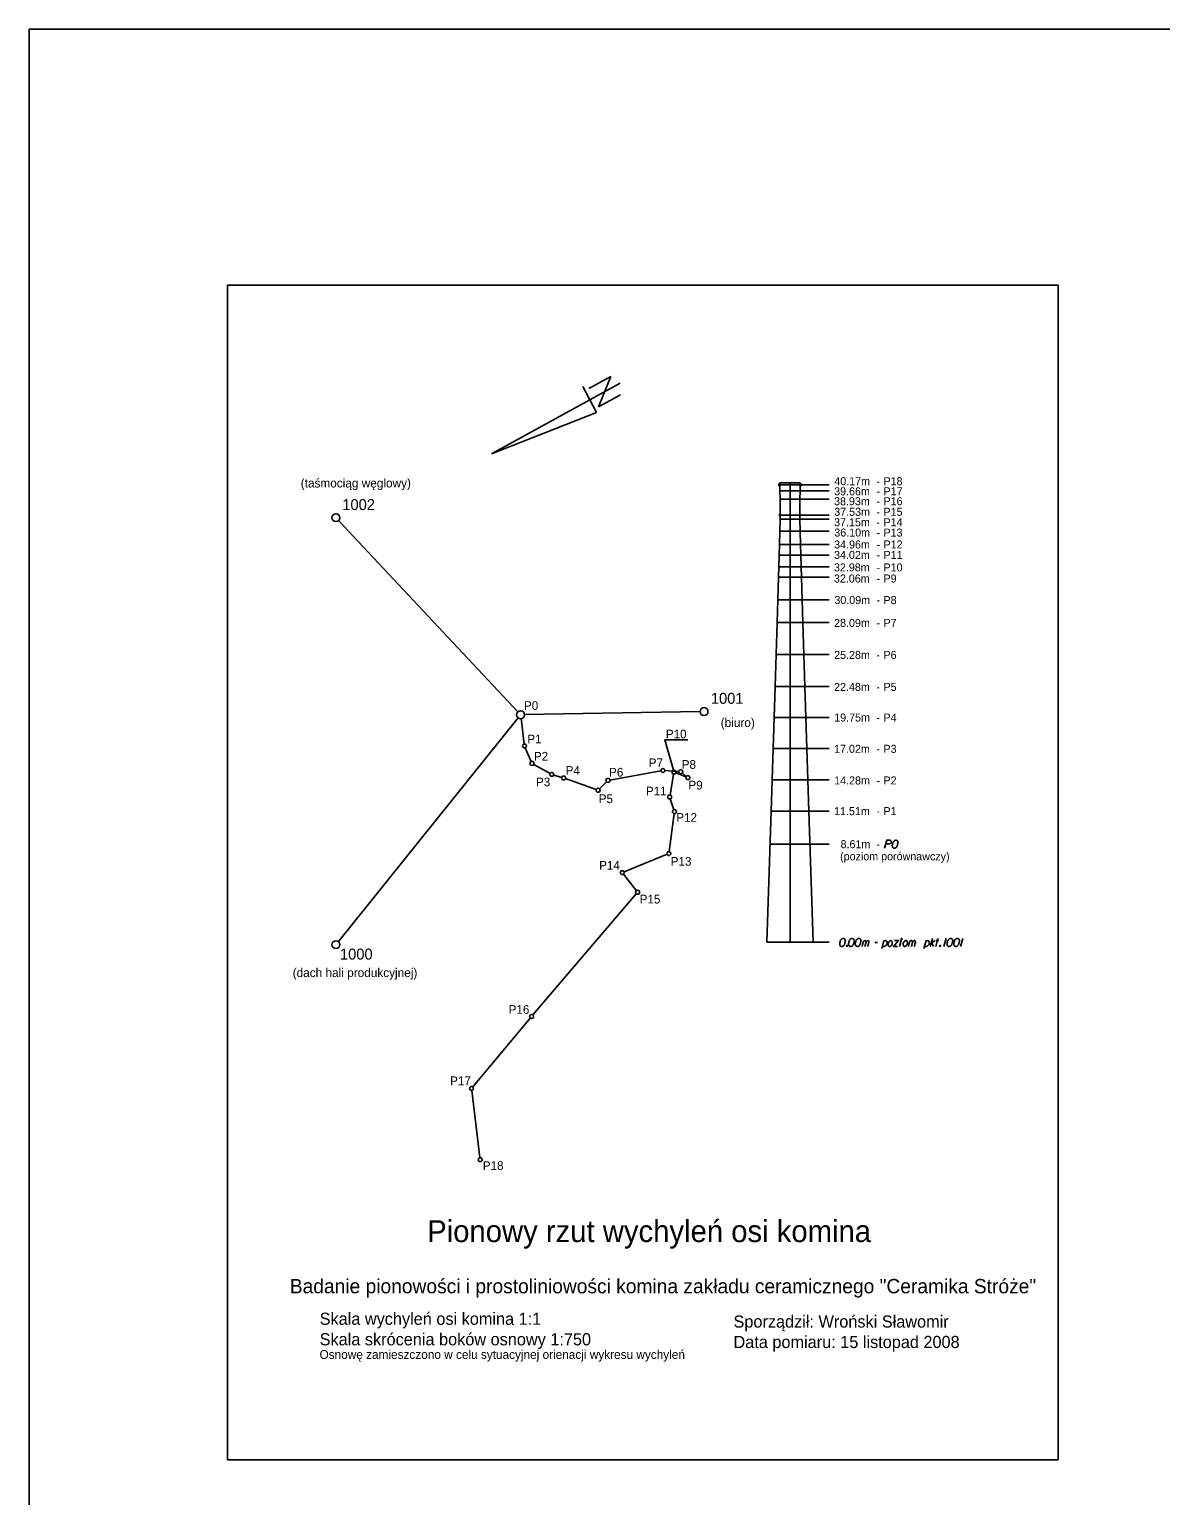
# Model space of a CAD drawing. Extents: x 138 to 264, y -75 to 121.
# Drawn here: x 137.94 to 166.54, y 1.58 to 38.66 of the extents above; entities that cross this region are included whole.
import ezdxf

# ---------------------------------------------------------------- set-up
doc = ezdxf.new("R2010")
doc.units = 0
for name, color, linetype in [('15 listopad 2008', 7, 'Continuous'), ('Opisy', 7, 'Continuous'), ('Ramka do drukowania', 7, 'Continuous'), ('Standart wykresów', 7, 'Continuous'), ('Wykresy 15 listopad 2008', 7, 'Continuous'), ('Wykresy 4 maj 2008', 7, 'Continuous')]:
    doc.layers.add(name, color=color, linetype=linetype)

msp = doc.modelspace()

# ---------------------------------------------------------------- linework, layer by layer
at = {"layer": '15 listopad 2008'}
msp.add_lwpolyline([(137.936, 38.661), (264.389, 38.661), (264.389, -75.347), (137.936, -75.347)], close=True, dxfattribs=at)
msp.add_lwpolyline([(154.222, 19.928), (154.003, 20.696), (154.583, 20.696)], dxfattribs=at)
at = {"layer": 'Opisy'}
for p, q in [((156.89, 27.165), (156.89, 27.141)), ((156.912, 27.165), (156.89, 27.165)), ((157.169, 27.141), (156.89, 27.141)), ((156.89, 27.141), (156.89, 27.116)), ((156.912, 27.116), (156.89, 27.116)), ((156.912, 27.19), (156.912, 27.165)), ((156.912, 27.19), (157.21, 27.19)), ((156.912, 26.993), (156.912, 27.116)), ((157.169, 15.575), (157.169, 27.19)), ((157.169, 27.141), (158.158, 27.141)), ((157.427, 27.19), (157.21, 27.19)), ((157.427, 27.19), (157.427, 27.165)), ((157.427, 27.165), (157.449, 27.165)), ((157.427, 27.116), (157.449, 27.116)), ((157.427, 26.993), (157.427, 27.116)), ((157.449, 27.165), (157.449, 27.141)), ((157.449, 27.141), (157.449, 27.116)), ((157.169, 26.993), (156.912, 26.993)), ((156.92, 26.783), (156.912, 26.993)), ((157.169, 26.783), (156.92, 26.783)), ((156.92, 26.783), (156.92, 26.405)), ((157.169, 26.993), (158.158, 26.993)), ((157.169, 26.783), (158.158, 26.783)), ((157.418, 26.783), (157.427, 26.993)), ((157.418, 26.783), (157.418, 26.405)), ((156.903, 26.405), (156.903, 26.379)), ((156.903, 26.405), (156.92, 26.405)), ((157.169, 26.379), (156.903, 26.379)), ((156.903, 26.379), (156.903, 26.354)), ((156.923, 26.354), (156.903, 26.354)), ((156.92, 26.271), (156.923, 26.354)), ((157.169, 26.379), (158.158, 26.379)), ((157.418, 26.271), (157.416, 26.354)), ((157.416, 26.354), (157.436, 26.354)), ((157.436, 26.405), (157.418, 26.405)), ((157.436, 26.405), (157.436, 26.379)), ((157.436, 26.379), (157.436, 26.354)), ((156.903, 25.638), (156.912, 25.967)), ((156.912, 25.967), (156.92, 26.271)), ((157.169, 25.967), (156.912, 25.967)), ((157.169, 26.271), (156.92, 26.271)), ((157.169, 26.271), (158.158, 26.271)), ((157.169, 25.967), (158.158, 25.967)), ((157.427, 25.967), (157.418, 26.271)), ((157.436, 25.638), (157.427, 25.967)), ((156.895, 25.368), (156.903, 25.638)), ((157.169, 25.638), (156.903, 25.638)), ((157.169, 25.638), (158.158, 25.638)), ((157.444, 25.368), (157.436, 25.638)), ((156.887, 25.069), (156.895, 25.368)), ((157.169, 25.368), (156.895, 25.368)), ((157.169, 25.368), (158.158, 25.368)), ((157.452, 25.069), (157.444, 25.368)), ((156.877, 24.804), (156.887, 25.069)), ((157.169, 25.069), (156.887, 25.069)), ((157.169, 25.069), (158.158, 25.069)), ((157.462, 24.804), (157.452, 25.069)), ((156.861, 24.236), (156.877, 24.804)), ((157.169, 24.804), (156.877, 24.804)), ((157.169, 24.804), (158.158, 24.804)), ((157.477, 24.236), (157.462, 24.804)), ((156.844, 23.662), (156.861, 24.236)), ((157.169, 24.236), (156.861, 24.236)), ((157.169, 24.236), (158.158, 24.236)), ((157.495, 23.662), (157.477, 24.236)), ((156.821, 22.851), (156.844, 23.662)), ((157.169, 23.662), (156.844, 23.662)), ((157.169, 23.662), (158.158, 23.662)), ((157.518, 22.851), (157.495, 23.662)), ((156.795, 22.047), (156.821, 22.851)), ((157.169, 22.851), (156.821, 22.851)), ((157.169, 22.851), (158.158, 22.851)), ((157.544, 22.047), (157.518, 22.851)), ((156.771, 21.261), (156.795, 22.047)), ((157.169, 22.047), (156.795, 22.047)), ((157.169, 22.047), (158.158, 22.047)), ((157.568, 21.261), (157.544, 22.047)), ((156.746, 20.476), (156.771, 21.261)), ((157.169, 21.261), (156.771, 21.261)), ((157.169, 21.261), (158.158, 21.261)), ((157.593, 20.476), (157.568, 21.261)), ((156.722, 19.685), (156.746, 20.476)), ((157.169, 20.476), (156.746, 20.476)), ((157.169, 20.476), (158.158, 20.476)), ((157.617, 19.685), (157.593, 20.476)), ((156.696, 18.889), (156.722, 19.685)), ((157.169, 19.685), (156.722, 19.685)), ((157.169, 19.685), (158.158, 19.685)), ((157.643, 18.889), (157.617, 19.685)), ((156.587, 15.575), (156.696, 18.889)), ((157.169, 18.889), (156.696, 18.889)), ((157.169, 18.889), (158.158, 18.889)), ((157.751, 15.575), (157.643, 18.889)), ((157.169, 18.053), (156.669, 18.053)), ((157.169, 18.053), (158.158, 18.053)), ((157.169, 15.575), (156.587, 15.575)), ((157.169, 15.575), (158.158, 15.575))]:
    msp.add_line(p, q, dxfattribs=at)
for points in [[(159.562, 17.955), (159.616, 18.158), (159.685, 18.158), (159.694, 18.156), (159.699, 18.155), (159.708, 18.15), (159.715, 18.145), (159.72, 18.139), (159.724, 18.131), (159.728, 18.119), (159.729, 18.11), (159.728, 18.102), (159.726, 18.096), (159.723, 18.089), (159.72, 18.084), (159.715, 18.078), (159.708, 18.073), (159.704, 18.07), (159.696, 18.067), (159.688, 18.065), (159.592, 18.065)], [(159.852, 18.158), (159.849, 18.158), (159.839, 18.156), (159.833, 18.155), (159.828, 18.153), (159.82, 18.15), (159.81, 18.145), (159.802, 18.14), (159.795, 18.134), (159.79, 18.127), (159.785, 18.119), (159.78, 18.111), (159.775, 18.102), (159.772, 18.096), (159.769, 18.086), (159.764, 18.07), (159.759, 18.046), (159.756, 18.027), (159.756, 18.009), (159.758, 17.997), (159.764, 17.982), (159.769, 17.974), (159.777, 17.965), (159.787, 17.959), (159.791, 17.957), (159.801, 17.955), (159.809, 17.955), (159.822, 17.957), (159.833, 17.96), (159.841, 17.965), (159.852, 17.973), (159.857, 17.978), (159.863, 17.984), (159.868, 17.99), (159.871, 17.995), (159.874, 18.003), (159.876, 18.006), (159.879, 18.014), (159.882, 18.024), (159.885, 18.033), (159.887, 18.04), (159.889, 18.045), (159.89, 18.051), (159.893, 18.065), (159.895, 18.073), (159.897, 18.081), (159.898, 18.092), (159.9, 18.107), (159.9, 18.111), (159.898, 18.118), (159.897, 18.124), (159.892, 18.134), (159.887, 18.14), (159.882, 18.145), (159.876, 18.15), (159.869, 18.153), (159.865, 18.155), (159.86, 18.156), (159.852, 18.158)], [(158.521, 15.673), (158.518, 15.673), (158.508, 15.672), (158.502, 15.67), (158.497, 15.668), (158.489, 15.665), (158.479, 15.66), (158.471, 15.656), (158.463, 15.649), (158.459, 15.643), (158.454, 15.635), (158.449, 15.627), (158.444, 15.617), (158.441, 15.611), (158.438, 15.601), (158.433, 15.586), (158.428, 15.562), (158.425, 15.543), (158.425, 15.525), (158.427, 15.512), (158.433, 15.498), (158.438, 15.49), (158.446, 15.48), (158.455, 15.474), (158.46, 15.472), (158.47, 15.471), (158.478, 15.471), (158.491, 15.472), (158.502, 15.476), (158.51, 15.48), (158.521, 15.488), (158.526, 15.493), (158.532, 15.499), (158.537, 15.506), (158.54, 15.511), (158.543, 15.519), (158.545, 15.522), (158.548, 15.53), (158.551, 15.539), (158.554, 15.549), (158.556, 15.555), (158.557, 15.56), (158.559, 15.566), (158.562, 15.581), (158.564, 15.589), (158.565, 15.597), (158.567, 15.608), (158.569, 15.622), (158.569, 15.627), (158.567, 15.633), (158.565, 15.64), (158.561, 15.649), (158.556, 15.656), (158.551, 15.66), (158.545, 15.665), (158.538, 15.668), (158.534, 15.67), (158.529, 15.672), (158.521, 15.673)], [(158.745, 15.673), (158.742, 15.673), (158.733, 15.672), (158.726, 15.67), (158.722, 15.668), (158.714, 15.665), (158.704, 15.66), (158.696, 15.656), (158.688, 15.649), (158.683, 15.643), (158.679, 15.635), (158.674, 15.627), (158.669, 15.617), (158.666, 15.611), (158.663, 15.601), (158.658, 15.586), (158.653, 15.562), (158.65, 15.543), (158.65, 15.525), (158.651, 15.512), (158.658, 15.498), (158.663, 15.49), (158.671, 15.48), (158.68, 15.474), (158.685, 15.472), (158.694, 15.471), (158.702, 15.471), (158.715, 15.472), (158.726, 15.476), (158.734, 15.48), (158.745, 15.488), (158.75, 15.493), (158.757, 15.499), (158.761, 15.506), (158.765, 15.511), (158.768, 15.519), (158.769, 15.522), (158.773, 15.53), (158.776, 15.539), (158.779, 15.549), (158.781, 15.555), (158.782, 15.56), (158.784, 15.566), (158.787, 15.581), (158.789, 15.589), (158.79, 15.597), (158.792, 15.608), (158.793, 15.622), (158.793, 15.627), (158.792, 15.633), (158.79, 15.64), (158.785, 15.649), (158.781, 15.656), (158.776, 15.66), (158.769, 15.665), (158.763, 15.668), (158.758, 15.67), (158.753, 15.672), (158.745, 15.673)], [(158.916, 15.673), (158.913, 15.673), (158.903, 15.672), (158.897, 15.67), (158.892, 15.668), (158.884, 15.665), (158.875, 15.66), (158.867, 15.656), (158.859, 15.649), (158.854, 15.643), (158.849, 15.635), (158.844, 15.627), (158.839, 15.617), (158.836, 15.611), (158.833, 15.601), (158.828, 15.586), (158.824, 15.562), (158.82, 15.543), (158.82, 15.525), (158.822, 15.512), (158.828, 15.498), (158.833, 15.49), (158.841, 15.48), (158.851, 15.474), (158.855, 15.472), (158.865, 15.471), (158.873, 15.471), (158.886, 15.472), (158.897, 15.476), (158.905, 15.48), (158.916, 15.488), (158.921, 15.493), (158.927, 15.499), (158.932, 15.506), (158.935, 15.511), (158.938, 15.519), (158.94, 15.522), (158.943, 15.53), (158.946, 15.539), (158.949, 15.549), (158.951, 15.555), (158.953, 15.56), (158.954, 15.566), (158.957, 15.581), (158.959, 15.589), (158.961, 15.597), (158.962, 15.608), (158.964, 15.622), (158.964, 15.627), (158.962, 15.633), (158.961, 15.64), (158.956, 15.649), (158.951, 15.656), (158.946, 15.66), (158.94, 15.665), (158.934, 15.668), (158.929, 15.67), (158.924, 15.672), (158.916, 15.673)], [(158.991, 15.471), (159.028, 15.616)], [(159.018, 15.578), (159.026, 15.595), (159.034, 15.605), (159.043, 15.611), (159.053, 15.616), (159.059, 15.619), (159.069, 15.619), (159.072, 15.617), (159.079, 15.611), (159.085, 15.603), (159.09, 15.589), (159.091, 15.581), (159.099, 15.595), (159.109, 15.605), (159.118, 15.611), (159.128, 15.616), (159.136, 15.619), (159.144, 15.619), (159.15, 15.617), (159.155, 15.611), (159.16, 15.603), (159.165, 15.589), (159.166, 15.581), (159.139, 15.471)], [(159.064, 15.471), (159.091, 15.581)], [(159.487, 15.418), (159.541, 15.617)], [(159.536, 15.6), (159.552, 15.613), (159.576, 15.617), (159.595, 15.614), (159.608, 15.605), (159.617, 15.592), (159.624, 15.574), (159.625, 15.558), (159.622, 15.544), (159.617, 15.527), (159.605, 15.507), (159.589, 15.49), (159.565, 15.474), (159.544, 15.471), (159.525, 15.472), (159.504, 15.484)], [(159.715, 15.617), (159.726, 15.617), (159.738, 15.611), (159.751, 15.594), (159.753, 15.586), (159.754, 15.578), (159.754, 15.571), (159.754, 15.547), (159.75, 15.531), (159.742, 15.512), (159.732, 15.496), (159.716, 15.482), (159.702, 15.471), (159.678, 15.471), (159.668, 15.474), (159.659, 15.482), (159.654, 15.49), (159.648, 15.509), (159.648, 15.538), (159.651, 15.547), (159.657, 15.568), (159.664, 15.579), (159.667, 15.586), (159.683, 15.603), (159.699, 15.613), (159.715, 15.617)], [(159.81, 15.621), (159.914, 15.621), (159.782, 15.471), (159.883, 15.471)], [(159.941, 15.471), (159.982, 15.625)], [(159.985, 15.673), (159.993, 15.673), (159.998, 15.67), (160.003, 15.664), (160.003, 15.656), (159.998, 15.649), (159.993, 15.646), (159.985, 15.646), (159.981, 15.649), (159.976, 15.656), (159.976, 15.664), (159.981, 15.67), (159.985, 15.673)], [(160.097, 15.617), (160.108, 15.617), (160.121, 15.611), (160.134, 15.594), (160.135, 15.586), (160.137, 15.578), (160.137, 15.571), (160.137, 15.547), (160.132, 15.531), (160.124, 15.512), (160.115, 15.496), (160.099, 15.482), (160.084, 15.471), (160.06, 15.471), (160.051, 15.474), (160.041, 15.482), (160.036, 15.49), (160.03, 15.509), (160.03, 15.538), (160.033, 15.547), (160.04, 15.568), (160.046, 15.579), (160.049, 15.586), (160.065, 15.603), (160.081, 15.613), (160.097, 15.617)], [(160.164, 15.471), (160.201, 15.616)], [(160.191, 15.578), (160.199, 15.595), (160.207, 15.605), (160.217, 15.611), (160.226, 15.616), (160.233, 15.619), (160.242, 15.619), (160.245, 15.617), (160.252, 15.611), (160.258, 15.603), (160.263, 15.589), (160.264, 15.581), (160.272, 15.595), (160.282, 15.605), (160.291, 15.611), (160.301, 15.616), (160.309, 15.619), (160.317, 15.619), (160.323, 15.617), (160.328, 15.611), (160.333, 15.603), (160.338, 15.589), (160.339, 15.581), (160.312, 15.471)], [(160.237, 15.471), (160.264, 15.581)], [(160.554, 15.418), (160.609, 15.617)], [(160.604, 15.6), (160.62, 15.613), (160.644, 15.617), (160.663, 15.614), (160.676, 15.605), (160.685, 15.592), (160.691, 15.574), (160.693, 15.558), (160.69, 15.544), (160.685, 15.527), (160.672, 15.507), (160.656, 15.49), (160.633, 15.474), (160.612, 15.471), (160.593, 15.472), (160.572, 15.484)], [(160.715, 15.471), (160.77, 15.673)], [(160.735, 15.543), (160.83, 15.622)], [(160.857, 15.471), (160.91, 15.673)], [(160.857, 15.617), (160.934, 15.617)], [(161.114, 15.673), (161.06, 15.471)], [(161.236, 15.673), (161.233, 15.673), (161.224, 15.672), (161.217, 15.67), (161.213, 15.668), (161.205, 15.665), (161.195, 15.66), (161.187, 15.656), (161.179, 15.649), (161.174, 15.643), (161.17, 15.635), (161.165, 15.627), (161.16, 15.617), (161.157, 15.611), (161.154, 15.601), (161.149, 15.586), (161.144, 15.562), (161.141, 15.543), (161.141, 15.525), (161.142, 15.512), (161.149, 15.498), (161.154, 15.49), (161.162, 15.48), (161.171, 15.474), (161.176, 15.472), (161.185, 15.471), (161.193, 15.471), (161.206, 15.472), (161.217, 15.476), (161.225, 15.48), (161.236, 15.488), (161.241, 15.493), (161.248, 15.499), (161.252, 15.506), (161.256, 15.511), (161.259, 15.519), (161.26, 15.522), (161.264, 15.53), (161.267, 15.539), (161.27, 15.549), (161.272, 15.555), (161.273, 15.56), (161.275, 15.566), (161.278, 15.581), (161.279, 15.589), (161.281, 15.597), (161.283, 15.608), (161.284, 15.622), (161.284, 15.627), (161.283, 15.633), (161.281, 15.64), (161.276, 15.649), (161.272, 15.656), (161.267, 15.66), (161.26, 15.665), (161.254, 15.668), (161.249, 15.67), (161.244, 15.672), (161.236, 15.673)], [(161.407, 15.673), (161.404, 15.673), (161.394, 15.672), (161.388, 15.67), (161.383, 15.668), (161.375, 15.665), (161.366, 15.66), (161.358, 15.656), (161.35, 15.649), (161.345, 15.643), (161.34, 15.635), (161.335, 15.627), (161.33, 15.617), (161.327, 15.611), (161.324, 15.601), (161.319, 15.586), (161.315, 15.562), (161.311, 15.543), (161.311, 15.525), (161.313, 15.512), (161.319, 15.498), (161.324, 15.49), (161.332, 15.48), (161.342, 15.474), (161.346, 15.472), (161.356, 15.471), (161.364, 15.471), (161.377, 15.472), (161.388, 15.476), (161.396, 15.48), (161.407, 15.488), (161.412, 15.493), (161.418, 15.499), (161.423, 15.506), (161.426, 15.511), (161.429, 15.519), (161.431, 15.522), (161.434, 15.53), (161.437, 15.539), (161.44, 15.549), (161.442, 15.555), (161.444, 15.56), (161.445, 15.566), (161.448, 15.581), (161.45, 15.589), (161.452, 15.597), (161.453, 15.608), (161.455, 15.622), (161.455, 15.627), (161.453, 15.633), (161.452, 15.64), (161.447, 15.649), (161.442, 15.656), (161.437, 15.66), (161.431, 15.665), (161.424, 15.668), (161.42, 15.67), (161.415, 15.672), (161.407, 15.673)], [(161.536, 15.673), (161.482, 15.471)], [(158.605, 15.498), (158.613, 15.498), (158.618, 15.495), (158.623, 15.488), (158.623, 15.48), (158.618, 15.474), (158.613, 15.471), (158.605, 15.471), (158.6, 15.474), (158.596, 15.48), (158.596, 15.488), (158.6, 15.495), (158.605, 15.498)], [(159.31, 15.573), (159.378, 15.573)], [(160.754, 15.558), (160.795, 15.471)], [(160.961, 15.498), (160.969, 15.498), (160.974, 15.495), (160.978, 15.488), (160.978, 15.48), (160.974, 15.474), (160.969, 15.471), (160.961, 15.471), (160.956, 15.474), (160.951, 15.48), (160.951, 15.488), (160.956, 15.495), (160.961, 15.498)]]:
    msp.add_lwpolyline(points, dxfattribs=at)
at = {"layer": 'Ramka do drukowania'}
for p, q in [((142.949, 2.492), (142.949, 32.192)), ((142.949, 32.192), (163.949, 32.192)), ((163.949, 2.492), (163.949, 32.192)), ((142.949, 2.492), (163.949, 2.492))]:
    msp.add_line(p, q, dxfattribs=at)
at = {"layer": 'Standart wykresów'}
for p, q in [((152.877, 29.711), (149.622, 27.93)), ((152.638, 29.879), (152.081, 29.582)), ((152.328, 29.119), (152.638, 29.879)), ((152.277, 28.974), (151.929, 29.632)), ((152.885, 29.415), (152.328, 29.119)), ((149.622, 27.93), (152.277, 28.974)), ((145.688, 26.313), (145.688, 26.313)), ((150.288, 21.402), (145.757, 26.24)), ((150.293, 21.251), (145.751, 15.593)), ((150.456, 21.331), (154.895, 21.407)), ((154.995, 21.408), (154.995, 21.408)), ((145.688, 15.515), (145.688, 15.515))]:
    msp.add_line(p, q, dxfattribs=at)
for centre in [(145.688, 26.313), (154.995, 21.408), (145.688, 15.515)]:
    msp.add_circle(centre, 0.1, dxfattribs=at)
at = {"layer": 'Wykresy 15 listopad 2008'}
for p, q in [((150.45, 20.589), (150.368, 21.23)), ((150.476, 20.494), (150.626, 20.145)), ((150.69, 20.075), (151.102, 19.844)), ((151.194, 19.805), (151.398, 19.744)), ((151.493, 19.713), (152.269, 19.436)), ((152.615, 19.678), (153.907, 19.911)), ((154.006, 19.916), (154.192, 19.904)), ((154.227, 19.83), (154.135, 19.299)), ((154.192, 19.904), (154.282, 19.898)), ((154.282, 19.898), (154.356, 19.893)), ((154.539, 19.758), (154.282, 19.861)), ((154.444, 19.857), (154.547, 19.771)), ((152.351, 19.455), (152.531, 19.634)), ((154.141, 19.202), (154.23, 18.927)), ((154.239, 18.83), (154.112, 17.869)), ((154.06, 17.801), (152.972, 17.358)), ((152.957, 17.3), (153.285, 16.879)), ((153.283, 16.801), (150.668, 13.737)), ((150.604, 13.661), (149.148, 11.918)), ((149.122, 11.83), (149.33, 10.129))]:
    msp.add_line(p, q, dxfattribs=at)
for centre, radius in [((150.356, 21.329), 0.1), ((150.456, 20.539), 0.05), ((150.646, 20.099), 0.05), ((151.146, 19.819), 0.05), ((151.446, 19.729), 0.05), ((152.566, 19.669), 0.05), ((153.956, 19.919), 0.05), ((154.236, 19.879), 0.05), ((154.406, 19.889), 0.05), ((154.586, 19.739), 0.05), ((152.316, 19.419), 0.05), ((154.126, 19.249), 0.05), ((154.246, 18.879), 0.05), ((154.106, 17.819), 0.05), ((152.926, 17.339), 0.05), ((153.316, 16.839), 0.05), ((150.636, 13.699), 0.05), ((149.116, 11.879), 0.05), ((149.336, 10.079), 0.05)]:
    msp.add_circle(centre, radius, dxfattribs=at)
at = {"layer": 'Wykresy 4 maj 2008'}
msp.add_circle((150.356, 21.329), 0.1, dxfattribs=at)

# ---------------------------------------------------------------- texts
at = {"layer": 'Opisy'}
for s, height, p in [('40.17m', 0.2024, (158.289, 27.133)), ('39.66m', 0.2024, (158.285, 26.878)), ('-', 0.202, (159.353, 27.133)), ('P18', 0.2024, (159.532, 27.133)), ('P17', 0.2024, (159.533, 26.878)), ('38.93m', 0.2024, (158.283, 26.627)), ('-', 0.202, (159.355, 26.878)), ('-', 0.202, (159.358, 26.627)), ('P16', 0.2024, (159.533, 26.627)), ('37.53m', 0.2024, (158.287, 26.359)), ('-', 0.202, (159.353, 26.359)), ('P15', 0.2024, (159.533, 26.359)), ('37.15m', 0.2024, (158.284, 26.095)), ('36.10m', 0.2024, (158.289, 25.835)), ('-', 0.202, (159.353, 26.095)), ('P14', 0.2024, (159.533, 26.095)), ('P13', 0.2024, (159.532, 25.835)), ('34.96m', 0.2024, (158.285, 25.533)), ('-', 0.202, (159.355, 25.835)), ('-', 0.202, (159.355, 25.533)), ('P12', 0.2024, (159.534, 25.533)), ('34.02m', 0.2024, (158.283, 25.269)), ('-', 0.202, (159.355, 25.269)), ('P11', 0.2024, (159.532, 25.269)), ('32.98m', 0.2024, (158.28, 24.954)), ('32.06m', 0.2024, (158.28, 24.673)), ('-', 0.202, (159.355, 24.954)), ('P10', 0.2024, (159.533, 24.954)), ('P9', 0.2024, (159.533, 24.673)), ('-', 0.202, (159.355, 24.673)), ('30.09m', 0.2024, (158.291, 24.129)), ('-', 0.202, (159.355, 24.129)), ('P8', 0.2024, (159.533, 24.126)), ('28.09m', 0.2024, (158.284, 23.55)), ('P7', 0.2024, (159.532, 23.55)), ('-', 0.202, (159.355, 23.55)), ('25.28m', 0.2024, (158.285, 22.741)), ('-', 0.202, (159.353, 22.741)), ('P6', 0.2024, (159.532, 22.741)), ('22.48m', 0.2024, (158.283, 21.932)), ('-', 0.202, (159.353, 21.932)), ('P5', 0.2024, (159.533, 21.932)), ('19.75m', 0.2024, (158.287, 21.158)), ('-', 0.202, (159.353, 21.158)), ('P4', 0.2024, (159.533, 21.158)), ('17.02m', 0.2024, (158.284, 20.366)), ('-', 0.202, (159.353, 20.366)), ('P3', 0.2024, (159.532, 20.366)), ('14.28m', 0.2024, (158.286, 19.566)), ('-', 0.202, (159.354, 19.566)), ('P2', 0.2024, (159.532, 19.566)), ('11.51m', 0.2024, (158.283, 18.791)), ('P1', 0.2024, (159.533, 18.791)), ('-', 0.202, (159.353, 18.791)), ('(poziom porównawczy)', 0.2024, (158.436, 17.648)), ('8.61m', 0.2024, (158.447, 17.955)), ('-', 0.202, (159.353, 17.955)), ('Pionowy rzut wychyleń osi komina', 0.55314, (147.995, 7.994)), ('Badanie pionowości i prostoliniowości komina zakładu ceramicznego "Ceramika Stróże"', 0.36281, (144.522, 6.699)), ('Skala wychyleń osi komina 1:1', 0.30766, (145.277, 5.902)), ('Sporządził: Wroński Sławomir', 0.30766, (155.74, 5.832)), ('Skala skrócenia boków osnowy 1:750', 0.30766, (145.277, 5.383)), ('Data pomiaru: 15 listopad 2008', 0.30766, (155.74, 5.315)), ('Osnowę zamieszczono w celu sytuacyjnej orienacji wykresu wychyleń', 0.22315, (145.274, 5.04))]:
    msp.add_text(s, height=height, dxfattribs=at).set_placement(p)
at = {"layer": 'Standart wykresów'}
for s, height, p in [('(taśmociąg węglowy)', 0.22315, (144.798, 27.076)), ('1002', 0.2771, (145.85, 26.505)), ('1001', 0.2771, (155.169, 21.605)), ('(biuro)', 0.2231, (155.417, 21.019)), ('1000', 0.2771, (145.791, 15.138)), ('(dach hali produkcyjnej)', 0.22315, (144.595, 14.696))]:
    msp.add_text(s, height=height, dxfattribs=at).set_placement(p)
at = {"layer": 'Wykresy 4 maj 2008'}
for s, p in [('P0', (150.444, 21.451)), ('P1', (150.527, 20.604)), ('P10', (154.03, 20.731)), ('P2', (150.694, 20.169)), ('P4', (151.497, 19.81)), ('P7', (153.598, 20.004)), ('P8', (154.432, 19.962)), ('P3', (150.747, 19.52)), ('P6', (152.594, 19.766)), ('P9', (154.601, 19.439)), ('P5', (152.334, 19.094)), ('P11', (153.525, 19.289)), ('P12', (154.293, 18.622)), ('P14', (152.343, 17.413)), ('P13', (154.153, 17.512)), ('P15', (153.369, 16.556)), ('P16', (150.055, 13.766)), ('P17', (148.576, 11.962)), ('P18', (149.402, 9.818))]:
    msp.add_text(s, height=0.22, dxfattribs=at).set_placement(p)

doc.saveas('drawing.dxf')
